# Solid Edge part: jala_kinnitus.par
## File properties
Author: Mac
Template: Normal.par
Last saved by: Mac
Revision: 10
Application: Solid Edge
Material: Aluminum, 1060
Face Style: Aluminum
Fill Style: ANSI38(Aluminum)
Virtual Style: Polished aluminum
Coef. of Thermal Exp: 2.3e-05
Thermal Conductivity: 221.0
Specific Heat: 920.0
Modulus of Elasticity: 68947570000.0
Poission's Ratio: 0.33
Yield Stress: 27579028.0
Ultimate Stress: 68947570.0
Elongation: 0.0
Density: 2712,000 kg/m^3
Accuracy: 0,990
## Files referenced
(..\..\..\Copy of copy of paat3\Asm15.asm
EC:\Documents and Settings\Mac\Desktop\Copy of copy of paat3\Asm15.asm
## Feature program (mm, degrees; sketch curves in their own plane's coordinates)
sketch for "unnamed Protrusion 1" plane through (0, -5.9734, 8.0273) normal (-1, 0, 0) x-axis (0, -1, 0)
extrude "unnamed Protrusion 1" add finite 0.4 along -normal
sketch for "ExtrudedProtrusion_3" plane through (0, 8.4266, 8.5708) normal (-1, 0, 0) x-axis (0, 0, 1)
extrude "ExtrudedProtrusion_3" add finite 0.1 along +normal
thinwall "Thinwall_6"  Thickness = 0.25 mm
sketch for "unnamed Protrusion 2" #1 plane through (-1.7003, 8.4266, 8.9492) normal (-0.978148, 0, 0.207912) x-axis (0, 1, 0)
sketch for "unnamed Protrusion 2" #2 plane through (-1.7003, 8.4266, 8.9492) normal (-0.978148, 0, 0.207912) x-axis (0, 1, 0)
extrude "unnamed Protrusion 2" add along -normal
sketch for "unnamed Cutout 1" #1 plane through (-1.387, 8.4266, 4.0952) normal (-0.207912, 0, -0.978148) x-axis (0.978148, 0, -0.207912)
sketch for "unnamed Cutout 1" #2 plane through (-1.387, 8.4266, 4.0952) normal (-0.207912, 0, -0.978148) x-axis (0.978148, 0, -0.207912)
extrude "unnamed Cutout 1" cut along -normal
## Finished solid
Body 1: solid body, 38 faces, 92 edges, 58 vertices.
  Faces by surface: plane 22, cylinder 16
  Edges by curve: line 60, circle 32
Bounding box of the edges (mm): 3.074 x 8.440 x 12.820, from (-2.6739, 4.2066, 2.1608) to (0.4, 12.6466, 14.9808).
Cylindrical faces by radius (mm): R0.3 x2, R0.5 x2, R0.74 x2, R1.34 x2, R1.59 x2, R2.6 x1, R2.85 x1, R3.37 x1, R3.45 x1, R3.62 x1, R4.22 x1
Planar faces by outward normal: +x 3, +y 5, -x 1, -y 5, oblique 8
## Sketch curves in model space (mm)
arc centre (0, 4.2366, 8.1064) radius 1.34 from (0, 5.5766, 8.1064) through (0, 5.5235, 8.4798) to (0, 5.3685, 8.8235)
arc centre (0, 8.4266, 10.7608) radius 3.62 from (0, 5.3685, 8.8235) through (0, 8.4266, 14.3808) to (0, 11.4846, 8.8235)
arc centre (0, 12.6166, 8.1064) radius 1.34 from (0, 11.4846, 8.8235) through (0, 11.3296, 8.4798) to (0, 11.2766, 8.1064)
line (0, 11.2766, 8.1064) -> (0, 11.2766, 5.6108)
arc centre (0, 8.4266, 5.6108) radius 2.85 from (0, 11.2766, 5.6108) through (0, 8.3421, 2.762) to (0, 5.5766, 5.6108)
line (0, 5.5766, 5.6108) -> (0, 5.5766, 8.1064)
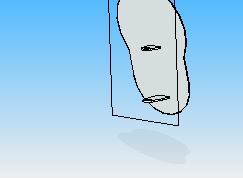
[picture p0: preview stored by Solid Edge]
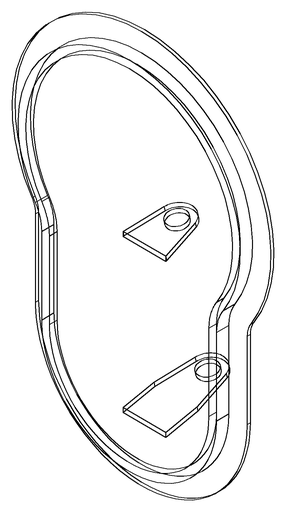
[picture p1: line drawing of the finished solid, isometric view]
